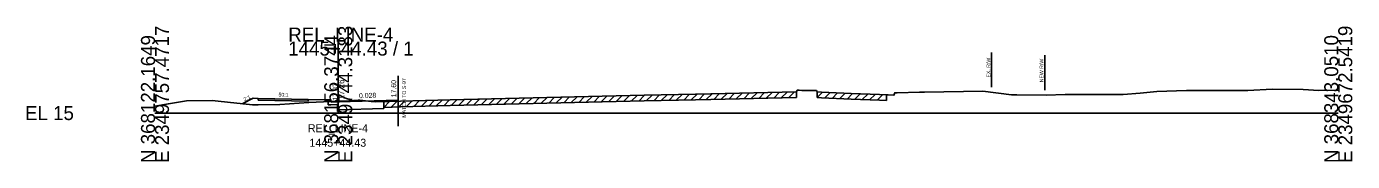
# Model space of a CAD drawing. Extents: x -26 to 2350146, y -10 to 368200.
# Drawn here: x 1974.3 to 2239.5, y 6490.3 to 6517.3 of the extents above; entities that cross this region are included whole.
import ezdxf

# ---------------------------------------------------------------- set-up
doc = ezdxf.new("R2010")
doc.units = 0
for name, color, linetype in [('RD_GPK_XS_Cell', 7, 'Continuous'), ('RD_XS_Base', 7, 'Continuous'), ('RD_XS_CurbBase', 7, 'Continuous'), ('RD_XS_CurbFront', 7, 'Continuous'), ('RD_XS_CurbTop', 7, 'Continuous'), ('RD_XS_EarthShd', 7, 'Continuous'), ('RD_XS_ExGround', 7, 'Continuous'), ('RD_XS_ExPaveRet', 7, 'Continuous'), ('RD_XS_ExRW', 7, 'Continuous'), ('RD_XS_NewRW', 7, 'Continuous'), ('RD_XS_Pave', 7, 'Continuous'), ('RD_XS_SW', 7, 'Continuous'), ('RD_XS_SWbase', 7, 'Continuous'), ('RD_XS_TieSlope', 7, 'Continuous'), ('RD_XS_TX_Elev_EX', 7, 'Continuous'), ('RD_XS_TX_Elev_PR', 7, 'Continuous'), ('RD_XS_TX_MatchLine', 7, 'Continuous'), ('RD_XS_TX_Slope', 7, 'Continuous'), ('RD_XS_TX_Station', 7, 'Continuous'), ('RD_XS_TX_TOC', 7, 'Continuous')]:
    doc.layers.add(name, color=color, linetype=linetype)

msp = doc.modelspace()

# ---------------------------------------------------------------- linework, layer by layer
at = {"layer": 'RD_GPK_XS_Cell'}
for p, q in [((2036.65, 6500), (2036.65, 6514.3)), ((2000, 6500), (2036.65, 6500)), ((2036.65, 6500), (2236.65, 6500))]:
    msp.add_line(p, q, dxfattribs=at)
at = {"layer": 'RD_XS_Base'}
for p, q in [((2036.65, 6500.62), (2045.74, 6500.88)), ((2045.74, 6500.88), (2045.74, 6502.29))]:
    msp.add_line(p, q, dxfattribs=at)
at = {"layer": 'RD_XS_CurbBase'}
for p, q in [((2034.65, 6502.66), (2034.65, 6501.66)), ((2034.65, 6501.66), (2035.15, 6501.66)), ((2035.15, 6501.66), (2036.65, 6501.74)), ((2036.65, 6500.62), (2036.65, 6501.74))]:
    msp.add_line(p, q, dxfattribs=at)
at = {"layer": 'RD_XS_CurbFront'}
msp.add_line((2036.65, 6501.74), (2036.65, 6502.24), dxfattribs=at)
at = {"layer": 'RD_XS_CurbTop'}
for p, q in [((2035.15, 6502.66), (2034.65, 6502.66)), ((2035.23, 6502.16), (2035.15, 6502.66)), ((2036.65, 6502.24), (2035.23, 6502.16)), ((2036.65, 6502.26), (2036.65, 6502.24))]:
    msp.add_line(p, q, dxfattribs=at)
at = {"layer": 'RD_XS_EarthShd'}
for p, q in [((2020.65, 6502.94), (2019.65, 6502.96)), ((2034.65, 6502.66), (2030.65, 6502.74))]:
    msp.add_line(p, q, dxfattribs=at)
at = {"layer": 'RD_XS_ExGround'}
msp.add_lwpolyline([(2000, 6501.35), (2002.69, 6501.87), (2006.33, 6502.42), (2011.42, 6502.5), (2012.62, 6502.37), (2019.48, 6501.63), (2020.66, 6501.65), (2024.98, 6501.69), (2030.79, 6502.12), (2036.65, 6502.37), (2038.79, 6502.46), (2040.62, 6502.57), (2040.97, 6502.58), (2041.6, 6502.52), (2043.26, 6502.32), (2044.11, 6502.24), (2049.13, 6502.37), (2059.02, 6502.65), (2083.88, 6503.26), (2092.21, 6503.46), (2097.82, 6503.57), (2108.12, 6503.8), (2111.18, 6503.87), (2128.28, 6504.25), (2128.44, 6504.55), (2128.8, 6504.55), (2129.38, 6504.53), (2131.92, 6504.52), (2132.27, 6504.52), (2132.43, 6504.22), (2133.27, 6504.18), (2139.2, 6503.9), (2144.87, 6503.7), (2146.28, 6503.65), (2146.64, 6503.63), (2147.78, 6503.57), (2147.94, 6504.07), (2148.44, 6504.07), (2152.91, 6504.15), (2153.3, 6504.15), (2153.91, 6504.16), (2165.56, 6504.36), (2171.29, 6503.67), (2171.85, 6503.67), (2172.39, 6503.62), (2178.21, 6503.57), (2182.05, 6503.7), (2190.46, 6503.71), (2193.64, 6503.69), (2197.04, 6503.96), (2200.38, 6504.33), (2206.3, 6504.51), (2211.89, 6504.5), (2213.88, 6504.5), (2217.82, 6504.49), (2218.57, 6504.54), (2223.45, 6504.77), (2229.6, 6504.74), (2232.74, 6504.5), (2236.65, 6504.61)], dxfattribs=at)
at = {"layer": 'RD_XS_ExPaveRet'}
for p, q in [((2045.74, 6501.14), (2046.92, 6502.32)), ((2047.24, 6501.18), (2048.42, 6502.35)), ((2048.74, 6501.22), (2049.92, 6502.39)), ((2050.24, 6501.26), (2051.42, 6502.44)), ((2051.74, 6501.3), (2052.92, 6502.48)), ((2053.24, 6501.34), (2054.42, 6502.52)), ((2054.74, 6501.38), (2055.92, 6502.56)), ((2056.24, 6501.43), (2057.42, 6502.6)), ((2057.74, 6501.47), (2058.92, 6502.64)), ((2059.24, 6501.51), (2060.41, 6502.68)), ((2060.74, 6501.55), (2061.91, 6502.72)), ((2062.24, 6501.58), (2063.41, 6502.75)), ((2063.74, 6501.62), (2064.91, 6502.79)), ((2065.24, 6501.66), (2066.41, 6502.83)), ((2066.74, 6501.69), (2067.91, 6502.86)), ((2068.24, 6501.73), (2069.41, 6502.9)), ((2069.74, 6501.77), (2070.91, 6502.94)), ((2071.24, 6501.8), (2072.41, 6502.97)), ((2072.74, 6501.84), (2073.91, 6503.01)), ((2074.24, 6501.88), (2075.41, 6503.05)), ((2075.74, 6501.91), (2076.91, 6503.09)), ((2077.24, 6501.95), (2078.41, 6503.12)), ((2078.74, 6501.99), (2079.91, 6503.16)), ((2080.24, 6502.02), (2081.41, 6503.2)), ((2081.74, 6502.06), (2082.91, 6503.23)), ((2083.24, 6502.1), (2084.42, 6503.27)), ((2083.88, 6502.11), (2092.21, 6502.32)), ((2084.74, 6502.13), (2085.92, 6503.31)), ((2086.24, 6502.17), (2087.42, 6503.34)), ((2087.74, 6502.21), (2088.92, 6503.38)), ((2089.24, 6502.25), (2090.42, 6503.42)), ((2090.74, 6502.28), (2091.92, 6503.46)), ((2092.21, 6502.32), (2097.82, 6502.43)), ((2092.24, 6502.32), (2093.41, 6503.49)), ((2093.74, 6502.35), (2094.91, 6503.52)), ((2095.24, 6502.38), (2096.41, 6503.54)), ((2096.74, 6502.41), (2097.91, 6503.57)), ((2097.82, 6502.43), (2108.12, 6502.66)), ((2098.24, 6502.44), (2099.41, 6503.61)), ((2099.74, 6502.47), (2100.91, 6503.64)), ((2101.24, 6502.5), (2102.41, 6503.67)), ((2102.74, 6502.54), (2103.91, 6503.71)), ((2104.24, 6502.57), (2105.41, 6503.74)), ((2105.74, 6502.6), (2106.91, 6503.77)), ((2107.24, 6502.64), (2108.41, 6503.81)), ((2108.12, 6502.66), (2111.18, 6502.72)), ((2108.74, 6502.67), (2109.91, 6503.84)), ((2110.24, 6502.7), (2111.41, 6503.87)), ((2111.18, 6502.72), (2128.28, 6503.11)), ((2111.74, 6502.74), (2112.91, 6503.91)), ((2113.24, 6502.77), (2114.41, 6503.94)), ((2114.74, 6502.8), (2115.91, 6503.97)), ((2116.24, 6502.84), (2117.41, 6504.01)), ((2117.74, 6502.87), (2118.91, 6504.04)), ((2119.24, 6502.91), (2120.41, 6504.08)), ((2120.74, 6502.94), (2121.91, 6504.11)), ((2122.24, 6502.97), (2123.41, 6504.14)), ((2123.74, 6503.01), (2124.91, 6504.18)), ((2125.24, 6503.04), (2126.41, 6504.21)), ((2126.74, 6503.08), (2127.91, 6504.25)), ((2128.28, 6504.25), (2128.28, 6503.11)), ((2132.43, 6503.08), (2132.43, 6504.22)), ((2132.43, 6503.08), (2133.53, 6504.17)), ((2132.43, 6503.08), (2133.27, 6503.04)), ((2133.27, 6503.04), (2139.2, 6502.75)), ((2133.93, 6503.01), (2135.02, 6504.1)), ((2135.43, 6502.94), (2136.52, 6504.03)), ((2136.93, 6502.86), (2138.02, 6503.95)), ((2138.43, 6502.79), (2139.53, 6503.89)), ((2139.2, 6502.75), (2144.87, 6502.55)), ((2139.93, 6502.73), (2141.04, 6503.83)), ((2141.43, 6502.68), (2142.54, 6503.78)), ((2142.93, 6502.62), (2144.04, 6503.73)), ((2144.43, 6502.57), (2145.54, 6503.68)), ((2144.87, 6502.55), (2146.28, 6502.51)), ((2146.28, 6503.65), (2146.28, 6502.51)), ((2045.74, 6501.14), (2045.74, 6502.29)), ((2045.74, 6501.14), (2049.13, 6501.23)), ((2049.13, 6501.23), (2059.02, 6501.5)), ((2059.02, 6501.5), (2083.88, 6502.11))]:
    msp.add_line(p, q, dxfattribs=at)
at = {"layer": 'RD_XS_ExRW'}
msp.add_line((2167.31, 6505.15), (2167.31, 6512.15), dxfattribs=at)
at = {"layer": 'RD_XS_NewRW'}
msp.add_line((2177.95, 6504.57), (2177.95, 6511.57), dxfattribs=at)
at = {"layer": 'RD_XS_Pave'}
for p, q in [((2048.65, 6497.4), (2048.65, 6507.42)), ((2036.65, 6502.26), (2048.65, 6502.6))]:
    msp.add_line(p, q, dxfattribs=at)
at = {"layer": 'RD_XS_SW'}
msp.add_line((2030.65, 6502.74), (2020.65, 6502.94), dxfattribs=at)
at = {"layer": 'RD_XS_SWbase'}
for p, q in [((2020.65, 6502.94), (2020.65, 6502.6)), ((2020.65, 6502.6), (2030.65, 6502.4)), ((2030.65, 6502.4), (2030.65, 6502.74))]:
    msp.add_line(p, q, dxfattribs=at)
at = {"layer": 'RD_XS_TieSlope'}
msp.add_line((2019.65, 6502.96), (2017.44, 6501.85), dxfattribs=at)

# ---------------------------------------------------------------- texts
at = {"layer": 'RD_GPK_XS_Cell'}
for s, p in [('E 2349757.4717', (2002.8, 6490)), ('E 2349744.3183', (2039.45, 6490)), ('E 2349672.5419', (2239.45, 6490)), ('N 368122.1649', (2000, 6490)), ('N 368156.3744', (2036.65, 6490)), ('N 368343.0510', (2236.65, 6490))]:
    msp.add_text(s, height=2.8, rotation=90, dxfattribs=at).set_placement(p)
for s, p in [('REL_LINE-4', (2026.65, 6514.3)), ('1445+44.43 / 1', (2026.65, 6511.5)), ('EL 15', (1974, 6498.6))]:
    msp.add_text(s, height=2.8, dxfattribs=at).set_placement(p)
at = {"layer": 'RD_XS_ExRW'}
msp.add_text('EX. R/W ', height=0.75, rotation=90, dxfattribs=at).set_placement((2167.06, 6507.1))
at = {"layer": 'RD_XS_NewRW'}
msp.add_text('NEW R/W ', height=0.75, rotation=90, dxfattribs=at).set_placement((2177.69, 6506.15))
at = {"layer": 'RD_XS_TX_Elev_EX'}
msp.add_text('17.37', height=1, rotation=90, dxfattribs=at).set_placement((2036.55, 6502.52))
at = {"layer": 'RD_XS_TX_Elev_PR'}
for s, height, rotation, p in [(' 17.26', 1.2, 90, (2037.85, 6502.26)), ('17.60', 1, 90, (2048.24, 6503.16)), ('0.028', 1, 1.6039, (2040.81, 6502.97))]:
    msp.add_text(s, height=height, rotation=rotation, dxfattribs=at).set_placement(p)
at = {"layer": 'RD_XS_TX_MatchLine'}
msp.add_text('MATCH TO S-97', height=0.75, rotation=90, dxfattribs=at).set_placement((2050.2, 6499.09))
at = {"layer": 'RD_XS_TX_Slope'}
for s, rotation, p in [('2:1', 26.5651, (2017.92, 6502.32)), ('50:1', 358.8542, (2024.69, 6503.31))]:
    msp.add_text(s, height=0.75, rotation=rotation, dxfattribs=at).set_placement(p)
at = {"layer": 'RD_XS_TX_Station'}
for s, p in [('REL_LINE-4', (2030.58, 6496.16)), ('1445+44.43', (2030.88, 6493.26))]:
    msp.add_text(s, height=1.6, dxfattribs=at).set_placement(p)
at = {"layer": 'RD_XS_TX_TOC'}
msp.add_text('TOCLT', height=0.05, dxfattribs=at).set_placement((2035.2, 6502.61))

doc.saveas('drawing.dxf')
